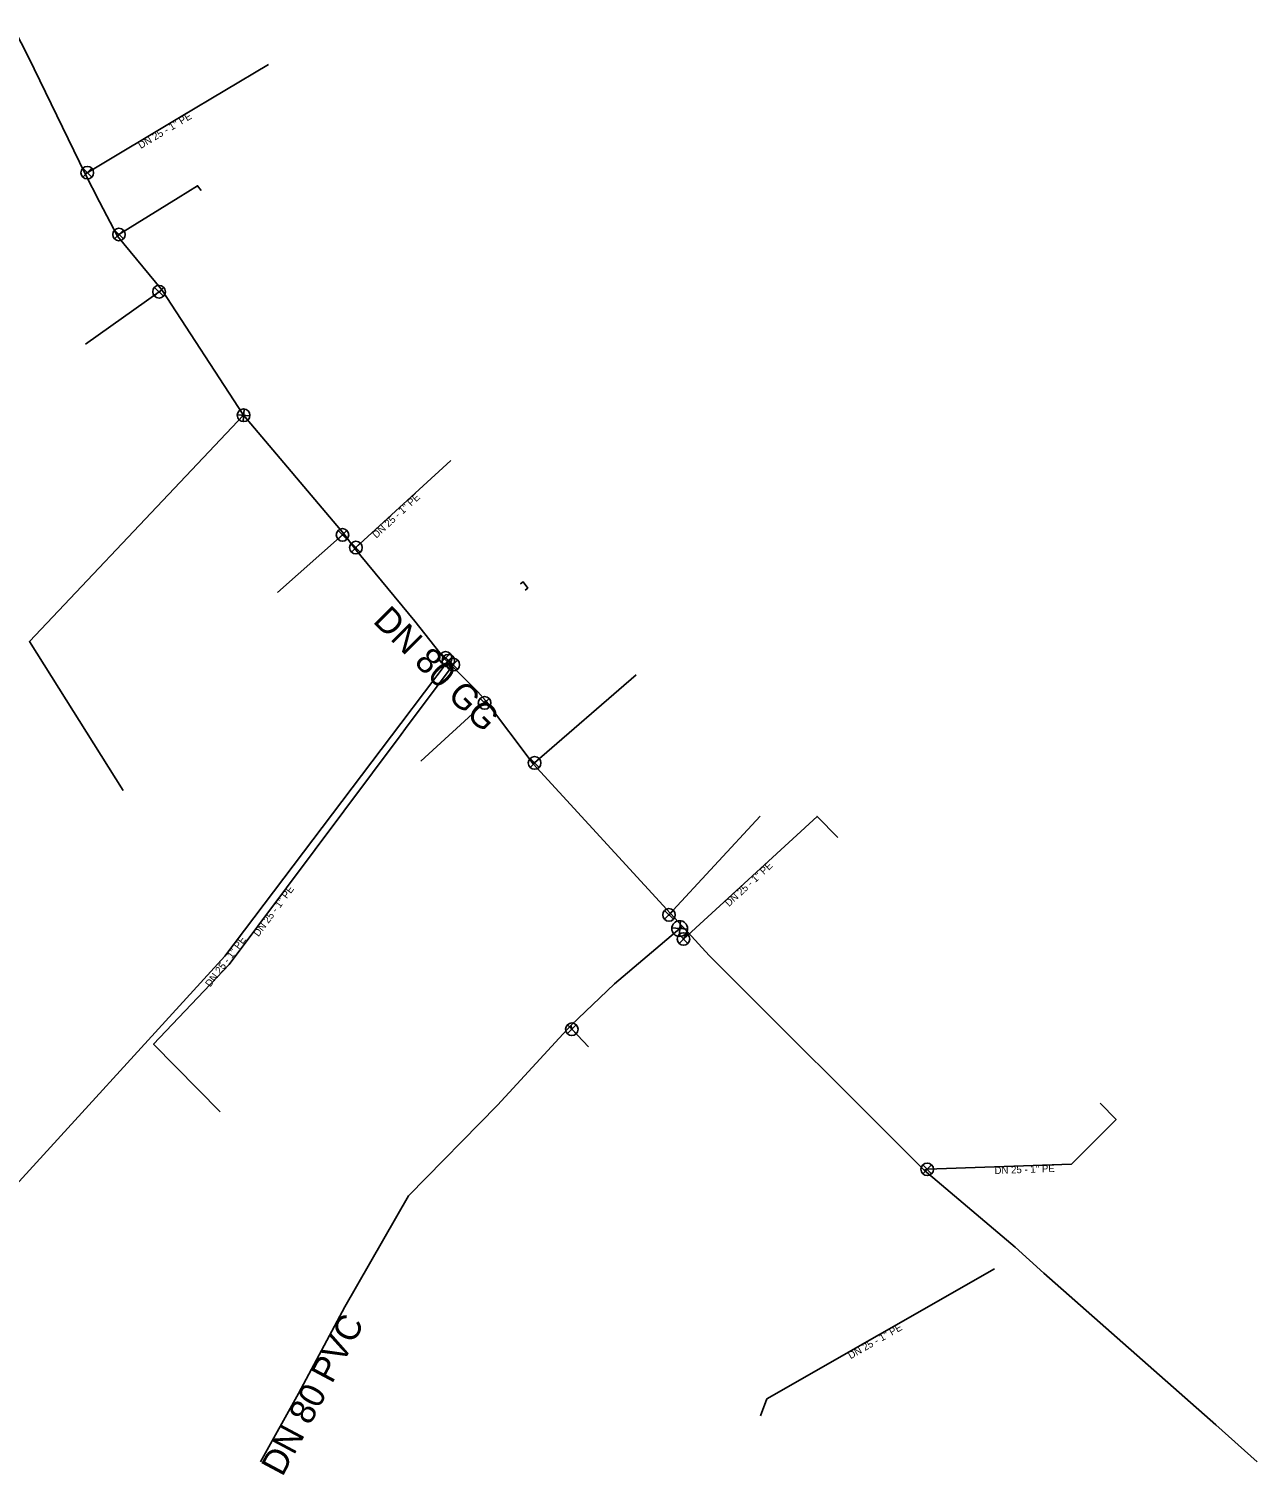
# Model space of a CAD drawing. Extents: x -484785 to -484462, y -1128039 to -1127627.
# Drawn here: x -484540.1 to -484462.2, y -1128039 to -1127947.3 of the extents above; entities that cross this region are included whole.
import ezdxf

# ---------------------------------------------------------------- set-up
doc = ezdxf.new("R2010")
doc.units = 0
for name, color, linetype in [('_pripojka_prevzato_z_dokumentace_', 7, 'Continuous'), ('_pripojka_priblizne_', 7, 'Continuous'), ('_voda_smvak_prevzato_z_dokumentace_', 7, 'Continuous'), ('Default', 7, 'Continuous'), ('MoLevel 27', 7, 'Continuous'), ('MoLevel 32', 7, 'Continuous'), ('MoLevel 43', 7, 'Continuous'), ('MoLevel 46', 7, 'Continuous'), ('MoLevel 53', 7, 'Continuous'), ('MoLevel 55', 7, 'Continuous')]:
    doc.layers.add(name, color=color, linetype=linetype)

# ---------------------------------------------------------------- blocks, each defined once
blk = doc.blocks.new('_uzaver_')
at = {"layer": 'Default'}
for p, q in [((-0.000035, -0.000035), (0.000035, 0.000035)), ((0.000035, -0.000035), (-0.000035, 0.000035))]:
    blk.add_line(p, q, dxfattribs=at)
for radius in [0.00005, 0.0000025]:
    blk.add_circle((0, 0), radius, dxfattribs=at)
blk = doc.blocks.new('_uzaver_pripojka_')
at = {"layer": 'Default'}
for p, q in [((-0.000035, -0.000035), (0.000035, 0.000035)), ((0.000035, -0.000035), (-0.000035, 0.000035))]:
    blk.add_line(p, q, dxfattribs=at)
for radius in [0.00005, 0.0000025]:
    blk.add_circle((0, 0), radius, dxfattribs=at)
blk = doc.blocks.new('_zaslepeni_')
at = {"layer": 'Default'}
blk.add_lwpolyline([(-0.00004, -0.00005), (0, -0.00005), (0, 0.00005), (-0.00004, 0.00005), (-0.00004, 0.00005)], dxfattribs=at)

msp = doc.modelspace()

# ---------------------------------------------------------------- linework, layer by layer
at = {"layer": '_pripojka_prevzato_z_dokumentace_'}
msp.add_line((-484530.443, -1127952.89), (-484524.912, -1127949.584), dxfattribs=at)
for points in [[(-484536.532, -1127956.516), (-484536.4, -1127956.45), (-484530.443, -1127952.89)], [(-484530.644, -1127958.041), (-484529.411, -1127957.275), (-484529.184, -1127957.589)], [(-484534.478, -1127960.474), (-484534.39, -1127960.37), (-484530.644, -1127958.041)], [(-484531.676, -1127963.881), (-484531.85, -1127964), (-484536.515, -1127967.315)], [(-484519.464, -1127980.256), (-484519.37, -1127980.22), (-484513.343, -1127974.703)], [(-484520.118, -1127979.356), (-484520.22, -1127979.41), (-484524.339, -1127983.058)], [(-484508.14, -1127993.922), (-484508.04, -1127993.87), (-484501.598, -1127988.28)], [(-484511.163, -1127989.903), (-484511.21, -1127990.06), (-484515.248, -1127993.751)], [(-484505.744, -1128010.507), (-484505.68, -1128010.75), (-484504.632, -1128011.868)], [(-484478.873, -1128025.934), (-484493.311, -1128034.183), (-484493.719, -1128035.254)]]:
    msp.add_lwpolyline(points, dxfattribs=at)
at = {"layer": '_pripojka_priblizne_'}
for p, q in [((-484526.49, -1127971.83), (-484530.143, -1127975.688)), ((-484516.218, -1127991.677), (-484516.504, -1127992.06))]:
    msp.add_line(p, q, dxfattribs=at)
for points in [[(-484530.143, -1127975.688), (-484540.07, -1127986.173), (-484534.118, -1127995.618)], [(-484513.597, -1127987.411), (-484513.51, -1127987.39), (-484516.522, -1127991.373)], [(-484513.325, -1127987.673), (-484513.2, -1127987.64), (-484516.218, -1127991.677)], [(-484516.522, -1127991.373), (-484527.67, -1128006.119), (-484542.52, -1128022.352)], [(-484516.504, -1127992.06), (-484527.407, -1128006.644), (-484532.2, -1128011.699), (-484527.971, -1128015.987)], [(-484499.415, -1128003.417), (-484499.52, -1128003.5), (-484493.73, -1127997.25)], [(-484498.327, -1128004.595), (-484498.6, -1128005.03), (-484490.128, -1127997.263), (-484488.817, -1127998.598)], [(-484474.004, -1128019.301), (-484471.176, -1128016.472), (-484472.186, -1128015.434)], [(-484483.342, -1128019.687), (-484483.15, -1128019.63), (-484474.004, -1128019.301)]]:
    msp.add_lwpolyline(points, dxfattribs=at)
at = {"layer": '_voda_smvak_prevzato_z_dokumentace_'}
msp.add_line((-484498.654, -1128004.24), (-484498.84, -1128004.37), dxfattribs=at)
for points in [[(-484552.394, -1127924.476), (-484546.544, -1127936.43), (-484542.52, -1127944.486), (-484540.129, -1127949.131), (-484536.532, -1127956.516), (-484535.627, -1127958.307), (-484534.478, -1127960.474), (-484531.676, -1127963.881), (-484526.49, -1127971.83)], [(-484526.49, -1127971.83), (-484520.118, -1127979.356), (-484519.464, -1127980.256), (-484515.636, -1127984.875), (-484513.731, -1127987.283), (-484513.597, -1127987.411), (-484513.325, -1127987.673), (-484511.629, -1127989.368), (-484511.163, -1127989.903), (-484508.14, -1127993.922), (-484499.415, -1128003.417), (-484498.654, -1128004.24)], [(-484498.84, -1128004.37), (-484502.967, -1128007.863), (-484505.744, -1128010.507), (-484510.397, -1128015.556), (-484516.029, -1128021.306), (-484520.079, -1128028.355), (-484523.006, -1128033.84), (-484525.425, -1128038.171)], [(-484462.236, -1128038.171), (-484464.847, -1128035.836), (-484475.755, -1128026.217), (-484477.581, -1128024.567), (-484483.342, -1128019.687), (-484496.968, -1128006.077), (-484498.327, -1128004.595), (-484498.654, -1128004.24)]]:
    msp.add_lwpolyline(points, dxfattribs=at)

# ---------------------------------------------------------------- block references
at = {"layer": 'MoLevel 27', "xscale": 10000, "yscale": 10000, "rotation": -139.74494292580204}
msp.add_blockref('_uzaver_', (-484498.84, -1128004.37), dxfattribs=at)
at = {"layer": 'MoLevel 43', "xscale": 5000, "yscale": 5000, "rotation": 36.97089948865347}
msp.add_blockref('_zaslepeni_', (-484508.623, -1127982.587), dxfattribs=at)
at = {"layer": 'MoLevel 53', "xscale": 7999.999999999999, "yscale": 7999.999999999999}
for p in [(-484536.4, -1127956.45), (-484534.39, -1127960.37), (-484531.85, -1127964), (-484520.22, -1127979.41), (-484519.37, -1127980.22), (-484513.68, -1127987.21), (-484513.51, -1127987.39), (-484513.2, -1127987.64), (-484511.21, -1127990.06), (-484508.04, -1127993.87), (-484499.52, -1128003.5), (-484498.6, -1128005.03), (-484505.68, -1128010.75), (-484483.15, -1128019.63)]:
    msp.add_blockref('_uzaver_pripojka_', p, dxfattribs=at)
at = {"layer": 'MoLevel 53', "xscale": 7999.999999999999, "yscale": 7999.999999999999, "rotation": -49.740970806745}
msp.add_blockref('_uzaver_pripojka_', (-484526.49, -1127971.83), dxfattribs=at)

# ---------------------------------------------------------------- texts
at = {"layer": 'MoLevel 32'}
for rotation, p in [(42.51412, (-484495.72, -1128003.007)), (53.21897, (-484525.547, -1128004.916)), (52.90902, (-484528.605, -1128008.11)), (2.06016, (-484478.872, -1128019.931))]:
    msp.add_text("DN 25 - 1'' PE", height=0.455, rotation=rotation, dxfattribs=at).set_placement(p)
at = {"layer": 'MoLevel 46'}
for s, rotation, p in [('DN 80 GG', 315.0169, (-484518.345, -1127984.925)), ('DN 80 PVC', 61.91396, (-484524.031, -1128039.169))]:
    msp.add_text(s, height=1.6049, rotation=rotation, dxfattribs=at).set_placement(p)
at = {"layer": 'MoLevel 55'}
for rotation, p in [(30.86537, (-484533.006, -1127954.952)), (42.47039, (-484518.077, -1127979.653)), (29.74112, (-484488.005, -1128031.675))]:
    msp.add_text("DN 25 - 1'' PE", height=0.455, rotation=rotation, dxfattribs=at).set_placement(p)

doc.saveas('drawing.dxf')
